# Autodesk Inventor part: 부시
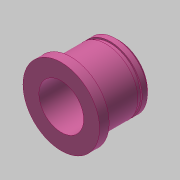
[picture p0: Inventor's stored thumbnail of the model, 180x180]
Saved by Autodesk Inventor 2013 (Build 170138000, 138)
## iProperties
Created: 2019-01
Part Number: 부시
Material: 강철, 연강
Document SubType Name: Modeling
Designer: mduedu
Density: 1 g/cm^3
Author: mduedu
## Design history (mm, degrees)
sketch "스케치1"
  geometry: L1 (0, 0)-(3, 0); L2 (3, 0)-(3, 12); L3 (3, 12)-(0, 12); L4 (0, 12)-(0, 0); L5 (3, 0)-(18, 0); L6 (18, 0)-(18, 10); L7 (18, 10)-(3, 10); L8 (3, 10)-(3, 0)
  constraints: 16 end point, 4 parallel, 2 horizontal, 2 perpendicular
  dimensions: "d0" = 18 distance between parallel lines of L6 L4; "d2" = 3 distance of L2.end L3.end; "d3" = 24 diameter of L3 L1; "d4" = 20 diameter of L7 L5
revolve "회전1" sketch "스케치1" stored, may be unused: angle "d5" = 90 deg
sketch "스케치2"
  geometry: C1 r 7 at (0, 0); 1 further point
  constraints: 1 centre point, 1 coincident
  dimensions: "d6" = 14 diameter of C1
extrude "돌출1" cut sketch "스케치2" stored distance "d7" = 10; taper "d8" = 0 deg
chamfer "모따기1" distance "d9" = 1; stored, may be unused: second distance "d10" = 2, angle "d11" = 45 deg
node "작업 평면1"
sketch "스케치3"
  geometry: C1 r 9.5 at (0, 0); C2 r 10 at (0, 0) reference; 1 further point
  constraints: 1 centre point, 1 coincident
  dimensions: "d13" = 19 diameter of C1
extrude "돌출2" cut sketch "스케치3" distance "d14" = 1.35; taper "d15" = 0 deg
node "솔리드1"
other parameters: "d12" = 11
